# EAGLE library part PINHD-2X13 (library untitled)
PIN HEADER
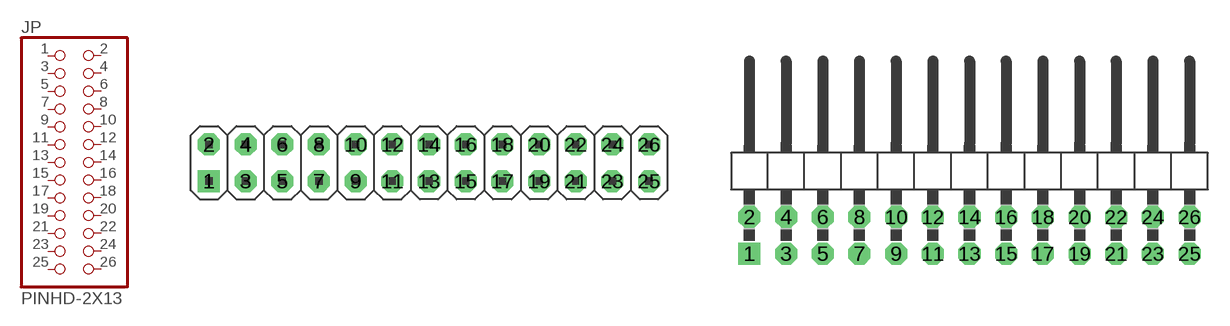
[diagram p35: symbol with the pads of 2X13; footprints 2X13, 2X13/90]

Designator prefix JP

## PINHD-2X13_2.54  [2X13]
1  1  pas
2  2  pas
3  3  pas
4  4  pas
5  5  pas
6  6  pas
7  7  pas
8  8  pas
9  9  pas
10  10  pas
11  11  pas
12  12  pas
13  13  pas
14  14  pas
15  15  pas
16  16  pas
17  17  pas
18  18  pas
19  19  pas
20  20  pas
21  21  pas
22  22  pas
23  23  pas
24  24  pas
25  25  pas
26  26  pas

## PINHD-2X13_2.54-90°  [2X13/90]
Pads as for 2X13

## PINHD-2X13_2.00  [2X13M]
Pads as for 2X13

## PINHD-2X13_2.54-SMD  [2X13SMD]
Pads as for 2X13

## PINHD-2X13  [2X13SMD/90]
Pads as for 2X13

## Footprint 2X13 (pad centres in mm)
PIN HEADER - 2.54
drill 1.016 square: 1 -15.24,-1.27
drill 1.016 octagon: 2 -15.24,1.27; 3 -12.7,-1.27; 4 -12.7,1.27; 5 -10.16,-1.27; 6 -10.16,1.27; 7 -7.62,-1.27; 8 -7.62,1.27; 9 -5.08,-1.27; 10 -5.08,1.27; 11 -2.54,-1.27; 12 -2.54,1.27; 13 0,-1.27; 14 0,1.27; 15 2.54,-1.27; 16 2.54,1.27; 17 5.08,-1.27; 18 5.08,1.27; 19 7.62,-1.27; 20 7.62,1.27; 21 10.16,-1.27; 22 10.16,1.27; 23 12.7,-1.27; 24 12.7,1.27; 25 15.24,-1.27; 26 15.24,1.27

## Footprint 2X13/90 (pad centres in mm)
PIN HEADER - 2.54 90°
drill 1.016 square: 1 -15.24,-6.35
drill 1.016 octagon: 2 -15.24,-3.81; 3 -12.7,-6.35; 4 -12.7,-3.81; 5 -10.16,-6.35; 6 -10.16,-3.81; 7 -7.62,-6.35; 8 -7.62,-3.81; 9 -5.08,-6.35; 10 -5.08,-3.81; 11 -2.54,-6.35; 12 -2.54,-3.81; 13 0,-6.35; 14 0,-3.81; 15 2.54,-6.35; 16 2.54,-3.81; 17 5.08,-6.35; 18 5.08,-3.81; 19 7.62,-6.35; 20 7.62,-3.81; 21 10.16,-6.35; 22 10.16,-3.81; 23 12.7,-6.35; 24 12.7,-3.81; 25 15.24,-6.35; 26 15.24,-3.81

## Footprint 2X13M (pad centres in mm)
PIN HEADER - 2
drill 0.914 square: 1 -12,-1
drill 0.914 round: 2 -12,1; 3 -10,-1; 4 -10,1; 5 -8,-1; 6 -8,1; 7 -6,-1; 8 -6,1; 9 -4,-1; 10 -4,1; 11 -2,-1; 12 -2,1; 13 0,-1; 14 0,1; 15 2,-1; 16 2,1; 17 4,-1; 18 4,1; 19 6,-1; 20 6,1; 21 8,-1; 22 8,1; 23 10,-1; 24 10,1; 25 12,-1; 26 12,1

## Footprint 2X13SMD (pad centres in mm)
PIN HEADER - 2.54 SMD
smd 1.016 x 3.302: 1 -1.27,-3.81; 2 -1.27,1.27; 3 1.27,-3.81; 4 1.27,1.27; 5 3.81,-3.81; 6 3.81,1.27; 7 6.35,-3.81; 8 6.35,1.27; 9 8.89,-3.81; 10 8.89,1.27; 11 11.43,-3.81; 12 11.43,1.27; 13 13.97,-3.81; 14 13.97,1.27; 15 16.51,-3.81; 16 16.51,1.27; 17 19.05,-3.81; 18 19.05,1.27; 19 21.59,-3.81; 20 21.59,1.27; 21 24.13,-3.81; 22 24.13,1.27; 23 26.67,-3.81; 24 26.67,1.27; 25 29.21,-3.81; 26 29.21,1.27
